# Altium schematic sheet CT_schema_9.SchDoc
size 278 x 170 mm
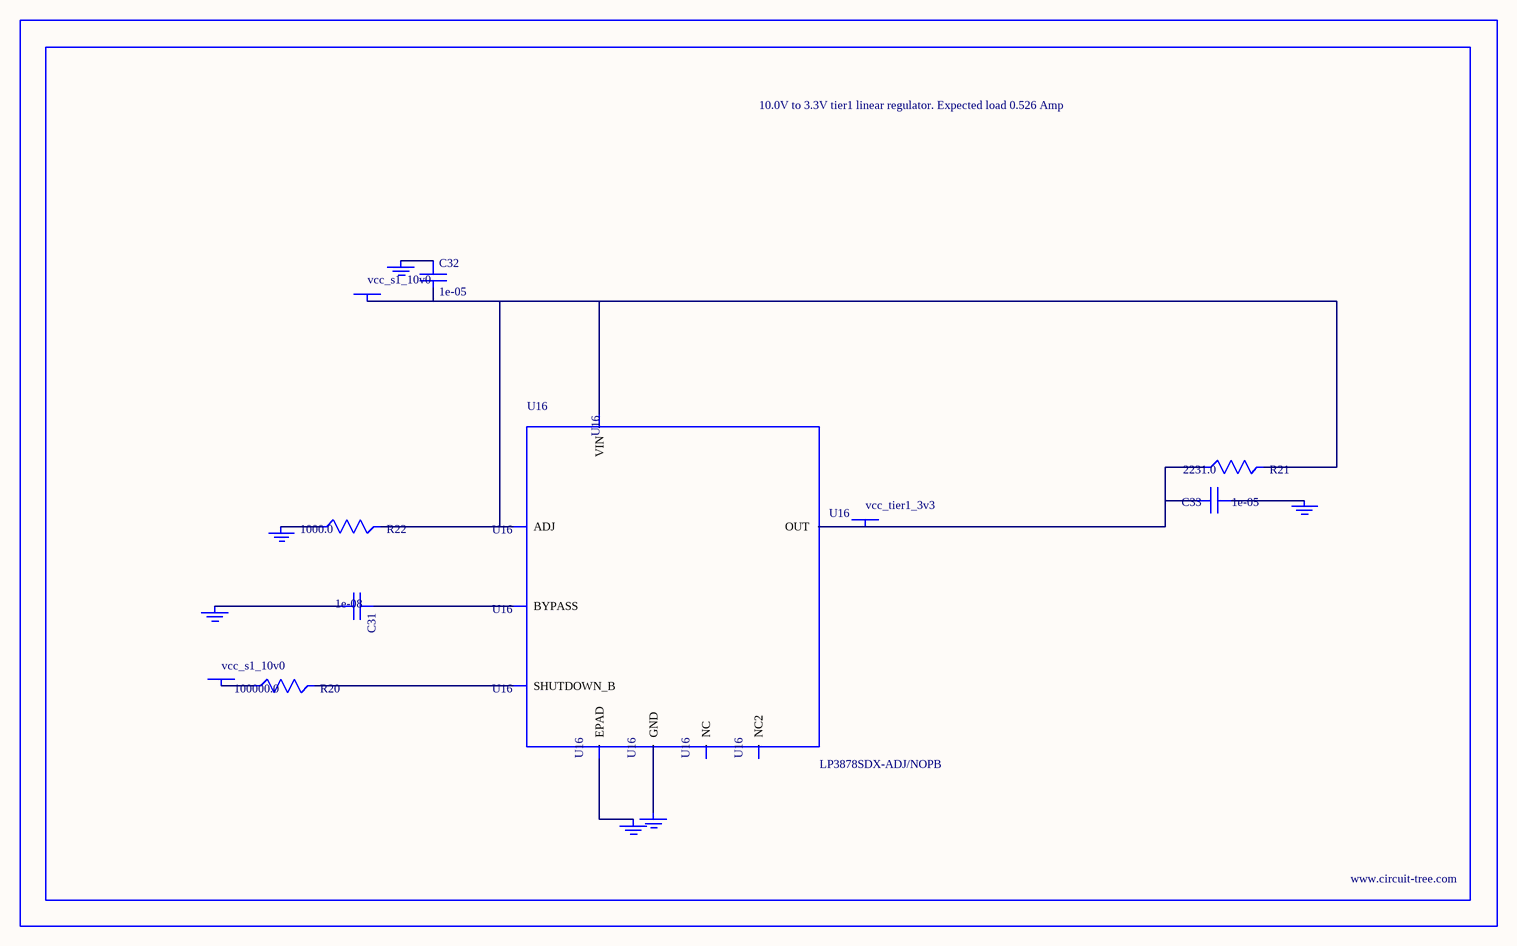
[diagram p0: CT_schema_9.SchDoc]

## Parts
BORDER8  (no value)
C31  1e-08  [C0402]
C32  1e-05  [C1206]
C33  1e-05  [C1210]
GND_INSTANCE_8_0  (no value)
GND_INSTANCE_8_1  (no value)
GND_INSTANCE_8_2  (no value)
GND_INSTANCE_8_3  (no value)
GND_INSTANCE_8_4  (no value)
GND_INSTANCE_8_5  (no value)
POWER_INSTANCE_8_0  vcc_s1_10v0
POWER_INSTANCE_8_1  vcc_s1_10v0
POWER_INSTANCE_8_2  vcc_tier1_3v3
R20  100000.0  [R0603]
R21  2231.0  [R0603]
R22  1000.0  [R0603]
U16  LP3878SDX-ADJ/NOPB  [WSON-8]

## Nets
NetC31_1: C31.1 U16.1(BYPASS)
NetC31_2: C31.2 GND_INSTANCE_8_0.0(GND)
NetC32_1: C32.1 GND_INSTANCE_8_1.0(GND)
NetC32_2: C32.2 POWER_INSTANCE_8_0.0(PWR) R21.2 R22.2 U16.4(VIN) U16.6(ADJ)
NetC33_1: C33.1 GND_INSTANCE_8_2.0(GND)
NetC33_2: C33.2 POWER_INSTANCE_8_2.0(PWR) R21.1 U16.5(OUT)
NetGND_INSTANCE_8_3_0: GND_INSTANCE_8_3.0(GND) R22.1
NetGND_INSTANCE_8_4_0: GND_INSTANCE_8_4.0(GND) U16.PAD(EPAD)
NetGND_INSTANCE_8_5_0: GND_INSTANCE_8_5.0(GND) U16.3(GND)
NetPOWER_INSTANCE_8_1_0: POWER_INSTANCE_8_1.0(PWR) R20.1
NetR20_2: R20.2 U16.8(SHUTDOWN_B)

Not connected (* = marked no-connect by the designer): U16 2(NC) 7(NC2)

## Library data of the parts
BORDER8 = BORDER_PAGE8
C31 = C0402C103K3RAC
C32 = C1206C106K3RACTU
C33 = GRM32DR61E106MA12L
GND_INSTANCE_8_0-GND_INSTANCE_8_5 = GND
POWER_INSTANCE_8_0-POWER_INSTANCE_8_2 = PWR
R20 = RC0603JR-07100KL
R21 = R21
R22 = RC0603JR-071KL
